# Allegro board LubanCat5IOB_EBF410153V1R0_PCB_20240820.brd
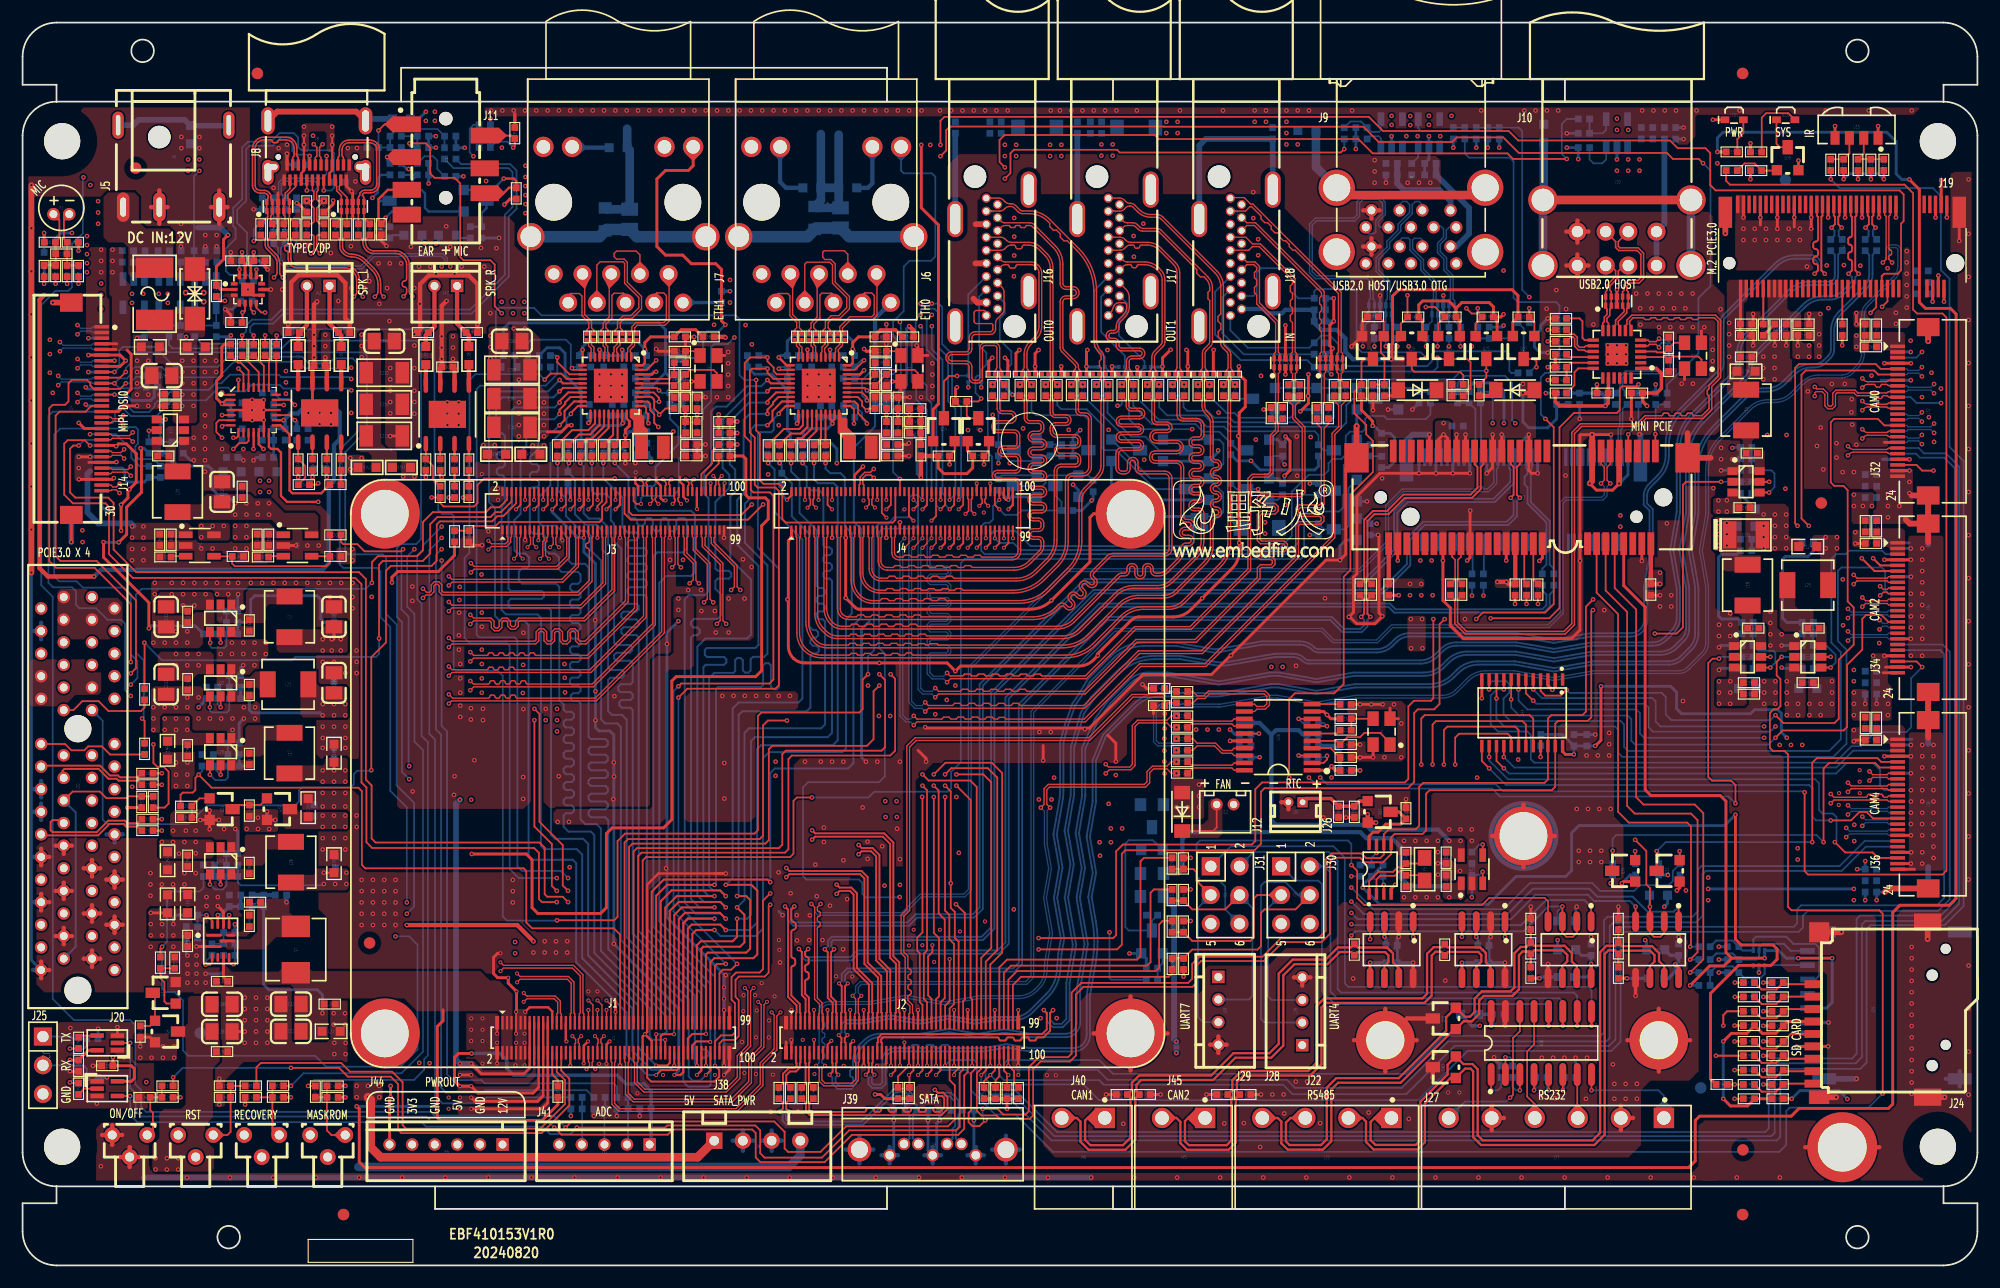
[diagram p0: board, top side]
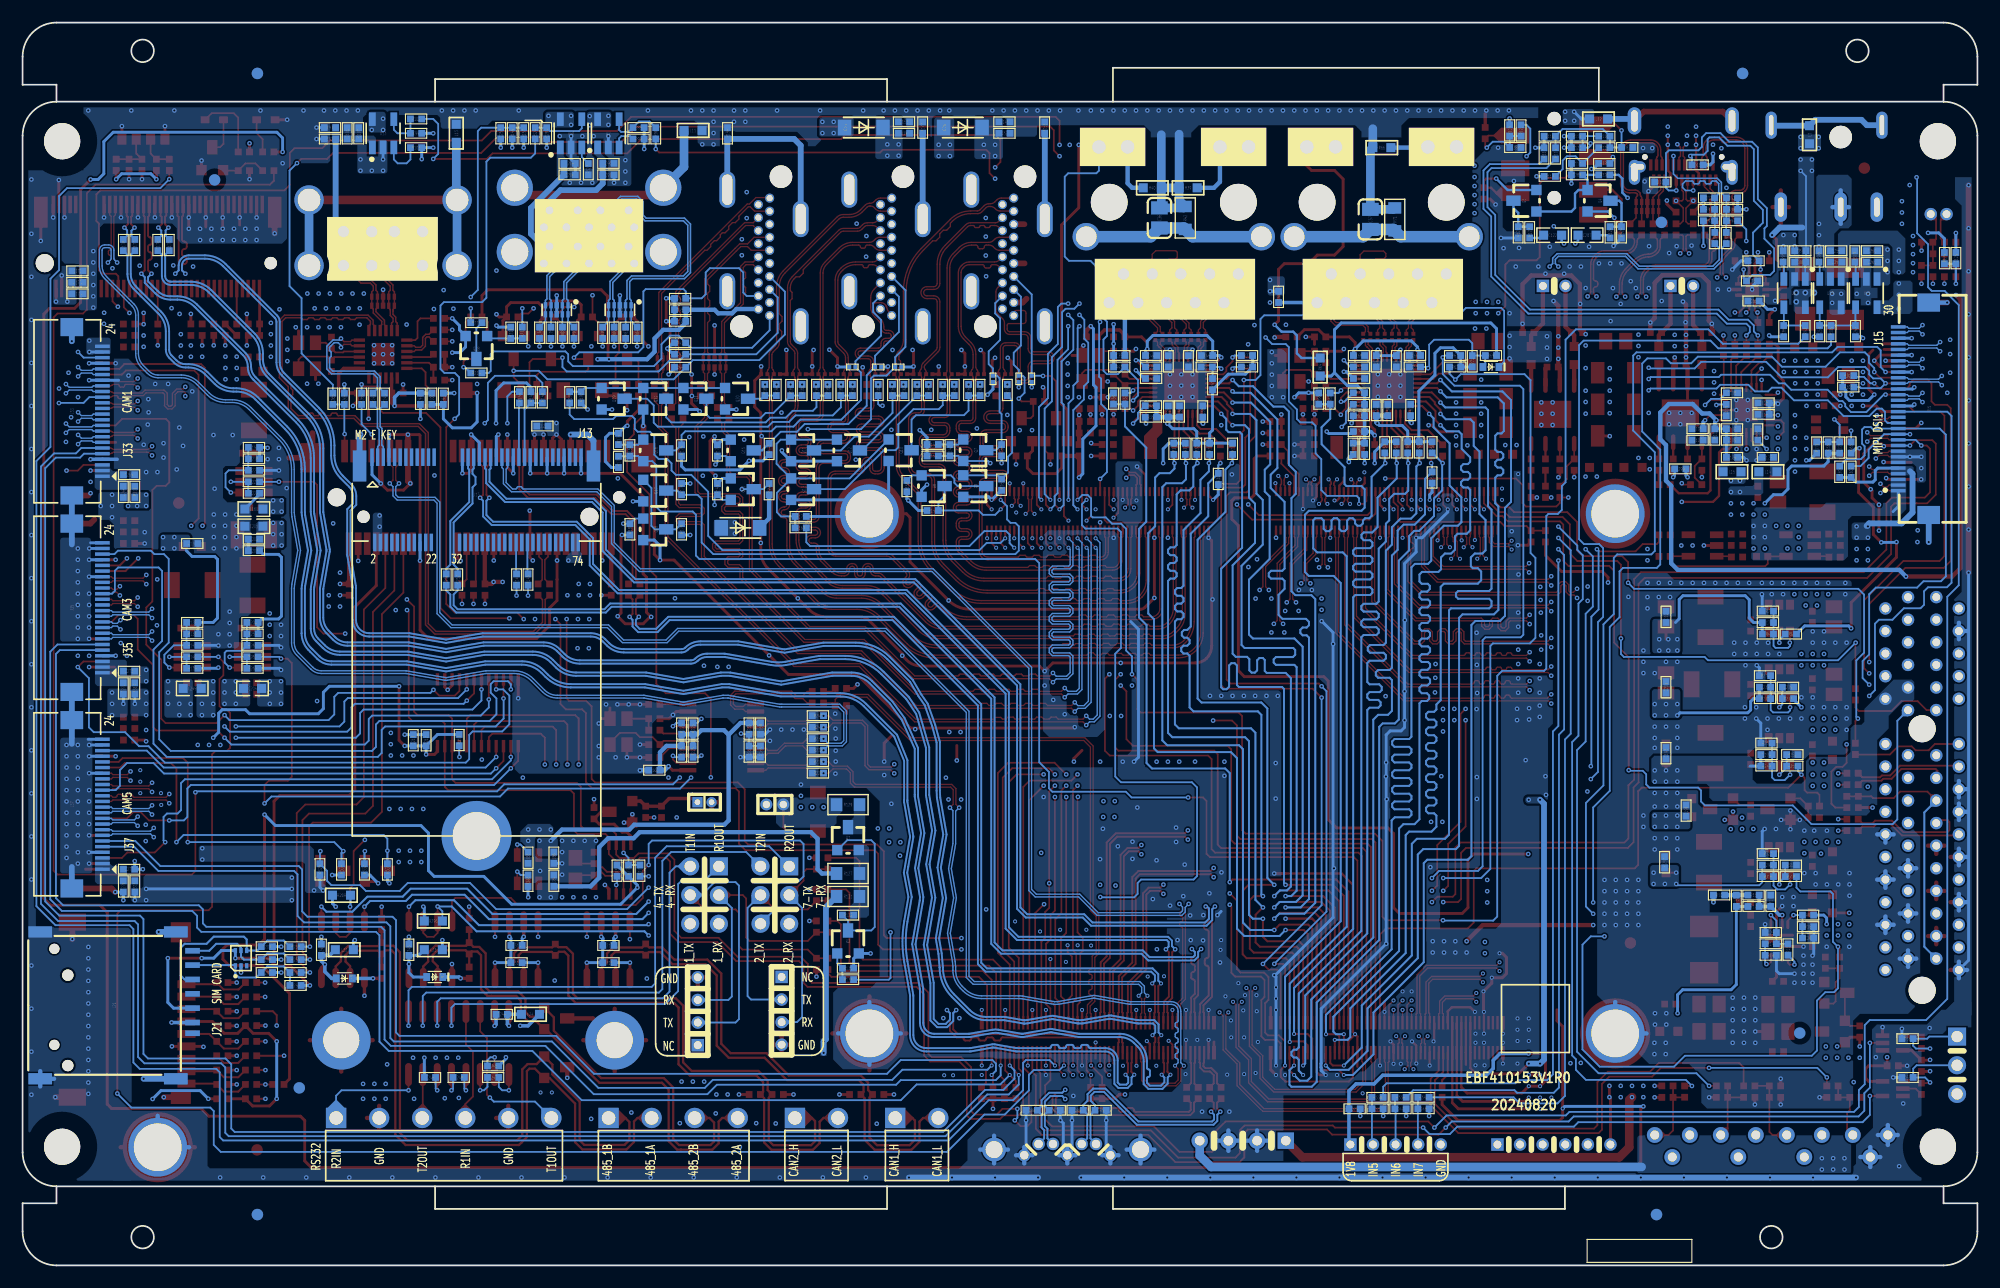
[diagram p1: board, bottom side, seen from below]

Outline 173 x 110 mm; copper layers: TOP, GND02, ART03, ART04, PWR05, BOTTOM. Coordinates in mm from the lower left corner of the outline.
Outline path: circle c10.62,107.5 r1 ; circle c18.24,2.5 r1 ; circle c162.38,107.5 r1 ; circle c162.38,2.5 r1 ; 3,103 arc(0.88,102.12) 0,100 0,10 arc(0.88,7.88) 3,7 ; 3,103 3,104.5 0,104.5 0,107 arc(0.88,109.12) 3,110 170,110 arc(172.12,109.12) 173,107 173,104.5 170,104.5 170,103 ; 3,103 170,103 ; 170,103 arc(172.12,102.12) 173,100 173,10 arc(172.12,7.88) 170,7 ; 3,7 3,5.5 0,5.5 0,3 arc(0.88,0.88) 3,0 170,0 arc(172.12,0.88) 173,3 173,5.5 170,5.5 170,7 ; 3,7 170,7 ; 33.5,103 33.5,106 76.5,106 76.5,103 ; 36.5,7 36.5,5 76.5,5 76.5,7 ; 96.5,103 96.5,105 136.5,105 136.5,103 ; 96.5,7 96.5,5 136.5,5 136.5,7

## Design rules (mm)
net group DP4: nets USB_HUB_DM2 USB_HUB_DP2
net group DP5: nets USB_HUB_DM1 USB_HUB_DP1
net group EKEY_PETN0: nets EKEY_PETN0 PCIE20_1_TXN
net group EKEY_PETP0: nets EKEY_PETP0 PCIE20_1_TXP
net group GMAC0_MCLKINOUT: nets GMAC0_MCLKINOUT PHY1_CLKOUT125
net group GMAC1_MCLKINOUT: nets GMAC1_MCLKINOUT PHY0_CLKOUT125
net group HDMI0_EARC+: nets HDMI0_EARC+ HDMI_TX0_SBDP
net group HDMI0_EARC-: nets HDMI0_EARC- HDMI_TX0_SBDN
net group HDMI1_EARC+: nets HDMI1_EARC+ HDMI_TX1_SBDP
net group HDMI1_EARC-: nets HDMI1_EARC- HDMI_TX1_SBDN
net group HDMI_RX0N_PORT: nets HDMI_RX0N_PORT HDMI_RX_D0N
net group HDMI_RX0P_PORT: nets HDMI_RX0P_PORT HDMI_RX_D0P
net group HDMI_RX1N_PORT: nets HDMI_RX1N_PORT HDMI_RX_D1N
net group HDMI_RX1P_PORT: nets HDMI_RX1P_PORT HDMI_RX_D1P
net group HDMI_RX2N_PORT: nets HDMI_RX2N_PORT HDMI_RX_D2N
net group HDMI_RX2P_PORT: nets HDMI_RX2P_PORT HDMI_RX_D2P
net group HDMI_RXCLKN_PORT: nets HDMI_RX_CLKN HDMI_RXCLKN_PORT
net group HDMI_RXCLKP_PORT: nets HDMI_RX_CLKP HDMI_RXCLKP_PORT
net group HDMI_TX0_D0N: nets HDMI_TX0_D0N HDMI_TX0_D0N_PORT
net group HDMI_TX0_D0P: nets HDMI_TX0_D0P HDMI_TX0_D0P_PORT
net group HDMI_TX0_D1N: nets HDMI_TX0_D1N HDMI_TX0_D1N_PORT
net group HDMI_TX0_D1P: nets HDMI_TX0_D1P HDMI_TX0_D1P_PORT
net group HDMI_TX0_D2N: nets HDMI_TX0_D2N HDMI_TX0_D2N_PORT
net group HDMI_TX0_D2P: nets HDMI_TX0_D2P HDMI_TX0_D2P_PORT
net group HDMI_TX0_D3N: nets HDMI_TX0_D3N HDMI_TX0_D3N_PORT
net group HDMI_TX0_D3P: nets HDMI_TX0_D3P HDMI_TX0_D3P_PORT
net group HDMI_TX1_D0N: nets HDMI_TX1_D0N HDMI_TX1_D0N_PORT
net group HDMI_TX1_D0P: nets HDMI_TX1_D0P HDMI_TX1_D0P_PORT
net group HDMI_TX1_D1N: nets HDMI_TX1_D1N HDMI_TX1_D1N_PORT
net group HDMI_TX1_D1P: nets HDMI_TX1_D1P HDMI_TX1_D1P_PORT
net group HDMI_TX1_D2N: nets HDMI_TX1_D2N HDMI_TX1_D2N_PORT
net group HDMI_TX1_D2P: nets HDMI_TX1_D2P HDMI_TX1_D2P_PORT
net group HDMI_TX1_D3N: nets HDMI_TX1_D3N HDMI_TX1_D3N_PORT
net group HDMI_TX1_D3P: nets HDMI_TX1_D3P HDMI_TX1_D3P_PORT
net group M2PCIE_REF_CLKN: nets M2PCIE_REF_CLKN N16803869
net group M2PCIE_REF_CLKP: nets M2PCIE_REF_CLKP N16803867
net group MDIN0_PHY0: nets MDIN0_PHY0 MDIN0_PHY0_RJ45
net group MDIN0_PHY1: nets MDIN0_PHY1 MDIN0_PHY1_RJ45
net group MDIN1_PHY0: nets MDIN1_PHY0 MDIN1_PHY0_RJ45
net group MDIN1_PHY1: nets MDIN1_PHY1 MDIN1_PHY1_RJ45
net group MDIN2_PHY0: nets MDIN2_PHY0 MDIN2_PHY0_RJ45
net group MDIN2_PHY1: nets MDIN2_PHY1 MDIN2_PHY1_RJ45
net group MDIN3_PHY0: nets MDIN3_PHY0 MDIN3_PHY0_RJ45
net group MDIN3_PHY1: nets MDIN3_PHY1 MDIN3_PHY1_RJ45
net group MDIP0_PHY0: nets MDIP0_PHY0 MDIP0_PHY0_RJ45
net group MDIP0_PHY1: nets MDIP0_PHY1 MDIP0_PHY1_RJ45
net group MDIP1_PHY0: nets MDIP1_PHY0 MDIP1_PHY0_RJ45
net group MDIP1_PHY1: nets MDIP1_PHY1 MDIP1_PHY1_RJ45
net group MDIP2_PHY0: nets MDIP2_PHY0 MDIP2_PHY0_RJ45
net group MDIP2_PHY1: nets MDIP2_PHY1 MDIP2_PHY1_RJ45
net group MDIP3_PHY0: nets MDIP3_PHY0 MDIP3_PHY0_RJ45
net group MDIP3_PHY1: nets MDIP3_PHY1 MDIP3_PHY1_RJ45
net group N16803965: nets N16803965 N16804075
net group PCIE20_1_REFCLK: nets PCIE20_1_REFCLKN PCIE20_1_REFCLKP
net group PCIE20_1_RX: nets PCIE20_1_RXN PCIE20_1_RXP
net group PCIE20_2_REFCLK: nets PCIE20_2_REFCLKN PCIE20_2_REFCLKP
net group PCIE20_2_RX: nets PCIE20_2_RXN PCIE20_2_RXP
net group PCIE20_2_TXN: nets PCIE20_2_TXN PE_TXN
net group PCIE20_2_TXP: nets PCIE20_2_TXP PE_TXP
net group PCIE30_PORT0_REF_CLKN: nets N16803772 PCIE30_PORT0_REF_CLKN
net group PCIE30_PORT0_REF_CLKP: nets N16803735 PCIE30_PORT0_REF_CLKP
net group PCIE30_PORT0_RX0: nets PCIE30_PORT0_RX0N PCIE30_PORT0_RX0P
net group PCIE30_PORT0_RX1: nets PCIE30_PORT0_RX1N PCIE30_PORT0_RX1P
net group PCIE30_PORT0_TX0N: nets PCIE30_PORT0_TX0N PETN0
net group PCIE30_PORT0_TX0P: nets PCIE30_PORT0_TX0P PETP0
net group PCIE30_PORT0_TX1N: nets PCIE30_PORT0_TX1N PETN1
net group PCIE30_PORT0_TX1P: nets PCIE30_PORT0_TX1P PETP1
net group PCIE30_PORT1_REF_CLKN: nets N16810873 PCIE30_PORT1_REF_CLKN
net group PCIE30_PORT1_REF_CLKP: nets N16810864 PCIE30_PORT1_REF_CLKP
net group PCIE30_PORT1_RX0: nets PCIE30_PORT1_RX0N PCIE30_PORT1_RX0P
net group PCIE30_PORT1_RX1: nets PCIE30_PORT1_RX1N PCIE30_PORT1_RX1P
net group PCIE30_PORT1_TX0N: nets PCIE30_PORT1_TX0N PCIEX4_PETN0
net group PCIE30_PORT1_TX0P: nets PCIE30_PORT1_TX0P PCIEX4_PETP0
net group PCIE30_PORT1_TX1N: nets PCIE30_PORT1_TX1N PCIEX4_PETN1
net group PCIE30_PORT1_TX1P: nets PCIE30_PORT1_TX1P PCIEX4_PETP1
net group PCIE30X1_0_CLKREQN_M0: nets N17044551 PCIE30X1_0_CLKREQN_M0
net group PCIE30X1_0_WAKEN_M0: nets N17044511 PCIE30X1_0_WAKEN_M0
net group PCIE30X1_1_CLKREQN_M1: nets N16843974 PCIE30X1_1_CLKREQN_M1
net group PCIE30X1_1_WAKEN_M1: nets N16843960 PCIE30X1_1_WAKEN_M1
net group PCIEX4_REF_CLKN: nets N16810480 PCIEX4_REF_CLKN
net group PCIEX4_REF_CLKP: nets N16810459 PCIEX4_REF_CLKP
net group PWM7_IR_M0: nets N16622302 PWM7_IR_M0
net group RTC_32K_IN: nets N16906410 RTC_32K_IN
net group SATA30_0_RXN: nets SATA30_0_RXN SATA_RXN
net group SATA30_0_RXP: nets SATA30_0_RXP SATA_RXP
net group SATA30_0_TXN: nets SATA30_0_TXN SATA_TXN
net group SATA30_0_TXP: nets SATA30_0_TXP SATA_TXP
net group TYPEC0_SBU1: nets TYPEC0_SBU1 TYPEC_SUB1
net group TYPEC0_SBU2: nets TYPEC0_SBU2 TYPEC_SUB2
net group TYPEC0_SSRX1N: nets TYPEC0_SSRX1N TYPEC_SSRXN1
net group TYPEC0_SSRX1P: nets TYPEC0_SSRX1P TYPEC_SSRXP1
net group TYPEC0_SSRX2N: nets TYPEC0_SSRX2N TYPEC_SSRXN2
net group TYPEC0_SSRX2P: nets TYPEC0_SSRX2P TYPEC_SSRXP2
net group TYPEC0_SSTX1N: nets TYPEC0_SSTX1N TYPEC_SSTXN1
net group TYPEC0_SSTX1P: nets TYPEC0_SSTX1P TYPEC_SSTXP1
net group TYPEC0_SSTX2N: nets TYPEC0_SSTX2N TYPEC_SSTXN2
net group TYPEC0_SSTX2P: nets TYPEC0_SSTX2P TYPEC_SSTXP2
net group TYPEC0_USB20_OTG_DM: nets TYPEC0_USB20_OTG_DM TYPEC_DM
net group TYPEC0_USB20_OTG_DP: nets TYPEC0_USB20_OTG_DP TYPEC_DP
net group TYPEC1_SSRX1: nets TYPEC1_SSRX1N TYPEC1_SSRX1P
net group TYPEC1_SSTX1: nets TYPEC1_SSTX1N TYPEC1_SSTX1P
net group TYPEC1_USB20_OTG_DM: nets TYPEC1_USB20_OTG_DM USB30_DM
net group TYPEC1_USB20_OTG_DP: nets TYPEC1_USB20_OTG_DP USB30_DP
net group USB20_DM1: nets USB20_DM1 USB20_HOST0_DM
net group USB20_DP1: nets USB20_DP1 USB20_HOST0_DP
net group USB20_HOST1_DM: nets N16621978 USB20_HOST1_DM
net group USB20_HOST1_DP: nets N16621974 USB20_HOST1_DP
net group USB30_RX: nets USB30_RXN USB30_RXP
net group USB30_TX: nets USB30_TXN USB30_TXP
net group USB_HUB_DM3: nets N16844509 USB_HUB_DM3
net group USB_HUB_DM4: nets N17044768 USB_HUB_DM4
net group USB_HUB_DP3: nets N16844471 USB_HUB_DP3
net group USB_HUB_DP4: nets N17044766 USB_HUB_DP4
net group 50_OHM: nets GMAC0_RXCLK GMAC0_RXD0 GMAC0_RXD1 GMAC0_RXD2 GMAC0_RXD3 GMAC0_RXDV_CRS GMAC1_RXCLK GMAC1_RXD0 GMAC1_RXD1 GMAC1_RXD2 GMAC1_RXD3 GMAC1_RXDV_CRS SDMMC_CLK SDMMC_CMD SDMMC_D0 SDMMC_D1 SDMMC_D2 SDMMC_D3
net group GMAC0_RXCLK: nets N16613010
net group GMAC0_RXD0: nets N16612988
net group GMAC0_RXD1: nets N16612992
net group GMAC0_RXD2: nets N16612996
net group GMAC0_RXD3: nets N16613006
net group GMAC0_RXDV_CRS: nets N16613014
net group GMAC1_RXCLK: nets N16607264
net group GMAC1_RXD0: nets N16607242
net group GMAC1_RXD1: nets N16607246
net group GMAC1_RXD2: nets N16607250
net group GMAC1_RXD3: nets N16607260
net group GMAC1_RXDV_CRS: nets N16607268
net group HDMI_GND: nets N16778784 N16781438 N16783799
net group PWR: nets 1V05_AVDD_PHY1 1V05_DVDD_PHY0 1V05_DVDD_PHY1 1V8_DVDD_PHY1 3V3_AVDD_PHY0 3V3_AVDD_PHY1 3V3_DVDD_PHY0 3V3_DVDD_PHY1 RS232_3V3 RS485_2_3V3 SIM_VDD VCC3V3_SD_S3 VCC_RTC
net group SDMMC_CLK: nets SD_CLK
net group SDMMC_CMD: nets SD_CMD
net group SDMMC_D0: nets SD_DAT0
net group SDMMC_D1: nets SD_DAT1
net group SDMMC_D2: nets SD_DAT2
net group SDMMC_D3: nets SD_DAT3
net group VCC3V3_PCIECLK: nets N16803673
net group VCC_3V3_S3: nets N16622154

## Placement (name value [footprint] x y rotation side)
C1  10uF  [C0603]  11.3 81.29 180 top
C2  10uF  [C0603]  15.37 81.29 0 top
C3  0.1uF  [C0402]  13.08 77.1 180 top
C4  NC  [C0402]  27.43 15.89 0 top
C5  NC  [C0402]  20.19 14.87 180 top
C6  0.1uF  [C0402]  20.07 56.64 90 top
C7  NC  [C0402]  18.54 56.89 0 bottom
C8  22uF  [C0805]  27.56 57.4 90 top
C9  10uF  [C0402]  152.78 14.75 180 top
C10  0.1uF  [C0402]  152.78 21.22 180 top
C11  0.1uF  [C0402]  27.56 57.4 90 bottom
C12  22uF  [C0805]  12.7 57.4 270 top
C13  0.1uF  [C0402]  14.61 57.4 270 top
C14  0.1uF  [C0402]  20.07 50.93 90 top
C15  0.1uF  [C0402]  17.91 15.89 180 top
C16  0.22uF  [C0402]  20.57 32.15 0 top
C17  10uF  [C0603]  12.83 32 90 top
C18  10uF  [C0603]  14.61 32.02 90 top
C19  0.1uF  [C0402]  14.61 28.72 270 top
C20  NC  [C0402]  21.34 32.27 270 bottom
C21  47uF  [C0805]  23.75 20.72 180 top
C22  47uF  [C0805]  23.75 23.13 180 top
C23  22uF  [C0603]  27.3 20.72 0 top
C24  0.1uF  [C0402]  27.18 23.13 0 top
C25  1uF  [C0402]  18.29 29.46 0 bottom
C26  0.1uF  [C0402]  14.99 28.97 180 bottom
C27  0.1uF  [C0402]  17.65 25.14 180 top
C28  0.1uF  [C0402]  12.83 14.87 0 top
C29  0.1uF  [C0402]  71.6 75.58 90 bottom
C30  0.1uF  [C0402]  70.61 75.58 90 bottom
C31  0.1uF  [C0402]  76.96 72.66 0 top
C32  4.7uF  [C0402]  76.96 71.64 0 top
C33  18pF  [C0402]  75.95 80.91 180 top
C34  18pF  [C0402]  76.45 78.37 270 top
C35  0.1uF  [C0402]  75.95 80.53 0 bottom
C36  1nF  [C0805]  72.39 92.71 90 bottom
C37  0.1uF  [C0402]  68.2 79.52 0 bottom
C38  0.1uF  [C0402]  68.55 75.58 90 bottom
C39  0.1uF  [C0402]  76.45 76.34 90 top
C40  0.1uF  [C0402]  71.6 80.02 270 bottom
C41  0.1uF  [C0402]  73.13 78.5 180 bottom
C42  0.1uF  [C0402]  77.47 76.34 90 top
C43  0.1uF  [C0402]  69.82 80.02 270 bottom
C44  0.1uF  [C0402]  73.13 80.53 180 bottom
C45  0.1uF  [C0402]  75.95 82.18 0 top
C46  0.1uF  [C0402]  68.17 80.53 0 bottom
C47  0.1uF  [C0402]  78.99 73.67 180 top
C48  0.1uF  [C0402]  78.99 75.83 180 top
C49  0.1uF  [C0402]  78.99 74.69 180 top
C50  0.1uF  [C0402]  52.19 75.71 90 bottom
C51  0.1uF  [C0402]  53.2 75.71 90 bottom
C52  0.1uF  [C0402]  59.18 72.66 0 top
C53  4.7uF  [C0402]  59.18 71.64 0 top
C54  18pF  [C0402]  58.17 80.91 180 top
C55  18pF  [C0402]  58.67 78.37 270 top
C56  0.1uF  [C0402]  61.85 85.72 90 bottom
C57  1nF  [C0805]  53.72 92.58 90 bottom
C58  0.1uF  [C0402]  49.78 79.52 0 bottom
C59  0.1uF  [C0402]  62.1 74.69 0 top
C60  0.1uF  [C0402]  59.69 76.34 90 top
C61  0.1uF  [C0402]  50.15 75.71 90 bottom
C62  0.1uF  [C0402]  51.42 80.02 270 bottom
C63  0.1uF  [C0402]  53.2 80.02 270 bottom
C64  0.1uF  [C0402]  54.73 78.5 180 bottom
C65  0.1uF  [C0402]  58.67 76.34 90 top
C66  0.1uF  [C0402]  49.77 80.53 0 bottom
C67  0.1uF  [C0402]  58.17 82.18 0 top
C68  0.1uF  [C0402]  54.73 80.53 180 bottom
C69  0.1uF  [C0402]  53.34 72.15 270 top
C70  0.1uF  [C0402]  54.74 73.8 0 bottom
C71  0.1uF  [C0402]  54.23 72.28 270 bottom
C72  10uF  [C0402]  18.92 88.91 180 top
C73  0.1uF  [C0402]  20.95 88.91 0 top
C74  0.1uF  [C0402]  17.14 86.25 270 top
C75  0.1uF  [C0402]  126.24 82.55 270 bottom
C76  0.1uF  [C0402]  127.25 82.55 270 bottom
C77  220pF  [C0402]  19.81 88.91 0 bottom
C78  220pF  [C0402]  19.94 87.14 180 bottom
C79  0.1uF  [C0402]  28.7 91.69 270 top
C80  0.1uF  [C0402]  27.69 91.69 270 top
C81  1uF  [C0402]  19.81 85.36 0 bottom
C82  0.1uF  [C0402]  22.1 91.69 270 top
C83  0.1uF  [C0402]  21.08 91.69 270 top
C84  0.1uF  [C0402]  23.24 90.93 270 bottom
C85  0.1uF  [C0402]  22.23 90.93 270 bottom
C86  0.1uF  [C0402]  17.14 82.69 270 bottom
C87  10uF  [C0402]  15.67 89.81 0 bottom
C88  0.1uF  [C0402]  15.67 88.8 0 bottom
C89  0.1uF  [C0402]  118.49 100.71 180 bottom
C90  10uF  [C0402]  121.16 97.53 180 bottom
C91  0.1uF  [C0402]  121.16 96.52 180 bottom
C92  1uF  [C0402]  145.8 99.69 0 bottom
C93  0.1uF  [C0402]  135.76 76.71 90 bottom
C94  4.7uF  [C0402]  137.79 76.71 270 bottom
C95  0.1uF  [C0402]  139.83 77.21 180 top
C96  0.1uF  [C0402]  142.88 77.21 180 top
C97  1uF  [C0402]  145.8 100.71 0 bottom
C98  0.1uF  [C0402]  136.14 78.36 180 top
C99  0.1uF  [C0402]  138.18 100.2 180 bottom
C100  10uF  [C0402]  143.26 100.2 90 bottom
C101  0.1uF  [C0402]  144.27 100.2 90 bottom
C102  NC  [C0402]  145.67 79.63 270 top
C103  NC  [C0402]  145.67 81.66 90 top
C104  0.1uF  [C0402]  162.43 97.41 270 top
C105  4.7uF  [C0402]  163.58 97.41 270 top
C106  0.1uF  [C0402]  24.77 74.06 0 bottom
C107  4.7uF  [C0402]  24.77 73.04 0 bottom
C108  0.1uF  [C0402]  18.92 76.34 0 bottom
C109  0.1uF  [C0402]  21.72 73.04 180 bottom
C110  4.7uF  [C0402]  21.72 74.06 180 bottom
C111  10uF  [C0402]  35.43 97.53 0 bottom
C112  1uF  [C0402]  19.43 81.02 90 top
C113  1uF  [C0402]  20.45 81.02 90 top
C114  0.1uF  [C0402]  18.92 75.33 0 bottom
C115  1uF  [C0402]  21.46 81.02 90 top
C116  270pF  [C0402]  37.85 99.95 0 bottom
C117  1uF  [C0402]  22.48 81.02 90 top
C118  10uF  [C0402]  21.72 77.23 180 bottom
C119  10uF  [C0402]  22.23 75.71 270 bottom
C120  10uF  [C0402]  19.43 73.55 90 bottom
C121  NC  [C0402]  35.43 98.93 0 bottom
C122  47uF  [C0603]  37.59 91.18 0 bottom
C123  10uF  [C0402]  18.54 71.52 0 bottom
C124  10uF  [C0402]  21.72 71.52 180 bottom
C125  4.7uF  [C0402]  1.91 89.15 90 bottom
C126  100pF  [C0402]  3.43 89.53 0 top
C127  0.1uF  [C0402]  158.5 56.4 180 top
C128  NC  [C0402]  157.99 56.91 180 bottom
C129  22uF  [C0603]  157.99 63.63 180 top
C130  0.1uF  [C0402]  157.99 63.9 180 bottom
C131  0.22uF  [C0402]  96.06 77.47 90 top
C132  0.22uF  [C0402]  95.05 77.47 90 top
C133  0.22uF  [C0402]  93.83 77.47 90 top
C134  0.22uF  [C0402]  92.81 77.47 90 top
C135  0.22uF  [C0402]  91.57 77.47 90 top
C136  0.22uF  [C0402]  90.55 77.47 90 top
C137  0.22uF  [C0402]  89.28 77.47 90 top
C138  0.22uF  [C0402]  88.27 77.47 90 top
C139  1uF  [C0402]  86.87 77.47 90 top
C140  1uF  [C0402]  85.85 77.47 90 top
C141  1uF  [C0402]  86.11 101.22 180 bottom
C142  100pF  [C0402]  90.93 72.15 270 bottom
C143  0.22uF  [C0402]  107.29 77.47 90 top
C144  0.22uF  [C0402]  106.27 77.47 90 top
C145  0.22uF  [C0402]  105.03 77.47 90 top
C146  0.22uF  [C0402]  104.01 77.47 90 top
C147  0.22uF  [C0402]  102.79 77.47 90 top
C148  0.22uF  [C0402]  101.78 77.47 90 top
C149  0.22uF  [C0402]  100.56 77.47 90 top
C150  0.22uF  [C0402]  99.54 77.47 90 top
C151  1uF  [C0402]  98.3 77.47 90 top
C152  1uF  [C0402]  97.28 77.47 90 top
C153  1uF  [C0402]  95 101.22 180 bottom
C154  100pF  [C0402]  119.25 72.13 270 bottom
C155  1uF  [C0402]  114.81 83.56 0 bottom
C156  0.1uF  [C0402]  153.03 71.9 180 top
C157  NC  [C0402]  152.53 72.4 180 bottom
C158  22uF  [C0603]  152.53 79.14 0 top
C159  0.1uF  [C0402]  152.53 80.41 0 top
C160  22uF  [C0603]  152.53 66.94 0 bottom
C161  0.1uF  [C0402]  152.4 67.07 0 top
C162  1uF  [C0402]  117.09 43.83 0 bottom
C163  0.1uF  [C0402]  117.09 43.81 0 top
C164  18pF  [C0402]  117.09 46.1 0 top
C165  18pF  [C0402]  117.09 48.39 180 top
C166  0.1uF  [C0402]  107.7 45.48 270 bottom
C167  1uF  [C0402]  108.71 45.48 270 bottom
C168  4.7uF  [C0402]  107.7 47.51 270 bottom
C169  0.1uF  [C0402]  157.61 83.33 0 top
C170  0.1uF  [C0402]  152.53 83.33 0 top
C171  0.1uF  [C0402]  152.53 82.31 0 top
C172  0.1uF  [C0402]  168.15 88.03 180 bottom
C173  0.1uF  [C0402]  168.15 87.01 180 bottom
C174  0.1uF  [C0402]  168.15 85.99 180 bottom
C175  0.22uF  [C0402]  160.02 90.31 90 bottom
C176  0.22uF  [C0402]  161.04 90.31 90 bottom
C177  0.22uF  [C0402]  163.07 90.31 90 bottom
C178  0.22uF  [C0402]  164.08 90.31 90 bottom
C179  0.1uF  [C0402]  20.07 44.83 90 top
C180  22uF  [C0603]  27.56 45.34 90 top
C181  0.1uF  [C0402]  157.61 82.31 0 top
C182  0.1uF  [C0402]  155.07 82.82 270 top
C183  0.1uF  [C0402]  156.08 82.82 270 top
C184  4.7uF  [C0402]  125.98 34.05 90 bottom
C185  0.1uF  [C0402]  125.98 34.05 90 top
C186  4.7uF  [C0402]  125.98 36.08 270 bottom
C187  0.1uF  [C0402]  125.98 36.08 270 top
C188  NC  [C0402]  128.27 36.08 270 bottom
C189  0.22uF  [C0402]  11.05 43.56 180 top
C190  0.22uF  [C0402]  11.05 42.54 180 top
C191  0.22uF  [C0402]  11.05 39.5 180 top
C192  0.22uF  [C0402]  11.05 38.48 180 top
C193  0.1uF  [C0402]  27.56 45.34 90 bottom
C194  NC  [C0402]  18.67 45.21 0 bottom
C195  22uF  [C0603]  12.83 45.59 270 top
C196  0.1uF  [C0402]  14.61 45.59 270 top
C197  22uF  [C0603]  25.27 40.51 90 top
C198  0.1uF  [C0402]  25.78 40.26 90 bottom
C199  0.1uF  [C0402]  153.16 56.4 0 top
C200  NC  [C0402]  152.65 56.91 0 bottom
C201  22uF  [C0603]  152.53 65.42 0 bottom
C202  1uF  [C0402]  152.53 64.28 0 bottom
C203  0.1uF  [C0402]  152.53 63.26 0 bottom
C204  22uF  [C0603]  152.65 51.07 0 bottom
C205  10uF  [C0402]  152.78 50.56 0 top
C206  0.1uF  [C0402]  152.78 51.58 0 top
C207  33pF  [C0402]  151.38 25.92 180 bottom
C208  33pF  [C0402]  151.38 27.07 180 bottom
C209  33pF  [C0402]  151.38 28.21 180 bottom
C210  47uF  [C1206]  32 79.01 0 top
C211  47uF  [C1206]  32 73.42 0 top
C212  10uF  [C0402]  137.29 46.48 90 bottom
C213  0.1uF  [C0402]  138.43 46.48 90 bottom
C214  0.1uF  [C0402]  119.38 59.82 90 top
C215  0.1uF  [C0402]  118.36 59.82 90 top
C216  0.1uF  [C0402]  121.16 26.8 0 bottom
C217  0.1uF  [C0402]  121.16 28.32 0 bottom
C218  47uF  [C1206]  32 76.21 0 top
C219  22uF  [C0805]  32 81.8 0 top
C220  0.1uF  [C0402]  120.9 59.82 270 top
C221  0.1uF  [C0402]  132.08 59.82 270 top
C222  0.1uF  [C0402]  127 74.29 0 bottom
C223  0.1uF  [C0402]  144.1 59.82 270 top
C224  0.1uF  [C0402]  12.45 71.64 0 top
C225  NC  [C0402]  12.19 72.39 270 bottom
C226  22uF  [C0805]  17.65 68.47 90 top
C227  0.1uF  [C0402]  19.43 68.47 90 top
C228  22uF  [C0805]  12.32 78.75 180 top
C229  0.1uF  [C0402]  13.08 76.09 180 top
C230  22uF  [C0805]  27.56 51.56 90 top
C231  0.1uF  [C0402]  27.56 51.18 90 bottom
C232  NC  [C0402]  18.8 51.18 0 bottom
C233  22uF  [C0805]  12.7 51.43 270 top
C234  0.1uF  [C0402]  14.61 51.43 270 top
C235  0.1uF  [C0402]  4.95 17.67 270 top
C236  0.1uF  [C0402]  7.49 17.67 180 top
C237  0.1uF  [C0402]  122.43 40.02 90 top
C238  10uF  [C0402]  117.86 40.15 270 top
C239  0.1uF  [C0402]  16.76 51.18 180 bottom
C240  18pF  [C0402]  122.43 36.07 90 top
C241  18pF  [C0402]  122.43 34.03 270 top
C242  0.1uF  [C0402]  146.56 27.94 90 bottom
C243  0.1uF  [C0402]  138.81 27.94 90 bottom
C244  0.1uF  [C0402]  130.6 22.22 0 bottom
C245  0.1uF  [C0402]  131.36 17.65 180 bottom
C246  0.1uF  [C0402]  136.95 16.64 0 bottom
C247  0.1uF  [C0402]  131.36 16.64 180 bottom
C248  0.1uF  [C0402]  134.41 16.64 180 bottom
C249  22uF  [C0603]  157.99 51.07 0 bottom
C250  0.1uF  [C0402]  157.99 51.58 0 top
C251  0.1uF  [C0402]  135.51 60.7 90 bottom
C252  0.1uF  [C0402]  134.49 60.7 90 bottom
C253  0.1uF  [C0402]  130.68 100.2 270 bottom
C254  10uF  [C0402]  20.77 64.23 270 top
C255  0.1uF  [C0402]  21.78 64.23 270 top
C256  10uF  [C0402]  12.5 89.81 0 bottom
C257  0.1uF  [C0402]  12.5 88.8 0 bottom
C258  0.1uF  [C0402]  27.69 62.75 0 top
C259  0.1uF  [C0402]  13.97 82.69 270 bottom
C260  10uF  [C0402]  9.32 89.81 0 bottom
C261  0.1uF  [C0402]  9.32 88.8 0 bottom
C262  0.1uF  [C0402]  10.79 82.69 270 bottom
C263  10uF  [C0402]  12.13 64.23 270 top
C264  0.1uF  [C0402]  13.15 64.23 270 top
C265  0.1uF  [C0402]  19.05 62.75 0 top
C266  10uF  [C0402]  164.08 68.47 270 bottom
C267  10uF  [C0402]  164.08 82.82 90 top
C268  0.1uF  [C0402]  163.58 81.29 180 top
C269  0.1uF  [C0402]  163.58 69.99 180 bottom
C270  10uF  [C0402]  164.08 65.42 90 top
C271  0.1uF  [C0402]  163.58 63.9 180 top
C272  10uF  [C0402]  164.08 51.07 270 bottom
C273  0.1uF  [C0402]  163.58 52.59 180 bottom
C274  10uF  [C0402]  164.08 48.02 90 top
C275  0.1uF  [C0402]  163.58 46.5 180 top
C276  10uF  [C0402]  164.08 33.54 270 bottom
C277  0.1uF  [C0402]  163.58 35.07 180 bottom
C278  0.1uF  [C0402]  26.29 79.64 180 top
C279  0.1uF  [C0402]  27.69 69.1 0 top
C280  22uF  [C0805]  17.65 23.11 0 top
C281  22uF  [C0805]  17.65 20.7 0 top
C282  0.1uF  [C0402]  17.65 18.92 0 top
C283  0.1uF  [C0402]  20.07 35.18 90 top
C284  0.1uF  [C0402]  126.62 100.2 270 bottom
C285  10uF  [C0402]  124.59 97.53 180 bottom
C286  0.1uF  [C0402]  124.59 96.52 180 bottom
C287  47uF  [C0603]  34.54 91.18 180 bottom
C288  0.1uF  [C0402]  40.89 98.95 180 bottom
C289  0.1uF  [C0402]  35.43 96.52 0 bottom
C290  NC  [C0402]  18.54 35.43 0 bottom
C291  22uF  [C0603]  27.56 35.56 90 top
C292  0.1uF  [C0402]  27.69 35.69 90 bottom
C293  22uF  [C0603]  12.83 35.81 270 top
C294  0.1uF  [C0402]  14.61 35.81 270 top
C295  10nF  [C0402]  68.96 15.25 270 top
C296  10nF  [C0402]  69.98 15.25 270 top
C297  10nF  [C0402]  67.94 15.25 270 top
C298  10nF  [C0402]  66.93 15.25 270 top
C299  0.1uF  [C0402]  26.29 70.5 0 bottom
C300  1nF  [C0402]  24 82.56 180 top
C301  1nF  [C0402]  28.45 82.56 0 top
C302  1uF  [C0402]  25.65 70.88 270 top
C303  47uF  [C1206]  43.31 74.18 0 top
C304  47uF  [C1206]  43.31 76.72 0 top
C305  47uF  [C1206]  43.31 79.26 0 top
C306  22uF  [C0805]  43.31 81.8 0 top
C307  0.1uF  [C0402]  37.59 79.52 180 top
C308  0.1uF  [C0402]  39.5 68.47 90 top
C309  0.1uF  [C0402]  38.23 68.47 90 top
C310  1nF  [C0402]  35.43 82.56 180 top
C311  1nF  [C0402]  39.75 82.56 0 top
C312  1uF  [C0402]  36.96 70.88 270 top
C313  0.1uF  [C0402]  129.29 26.8 0 bottom
C314  0.1uF  [C0402]  129.29 28.32 0 bottom
C315  220uF  [CASE-B_3528]  152.53 64.66 0 top
C316  NC  [C0402]  119.51 83.96 180 top
D1  SMAJ13CA  [SMA_CA]  15.24 85.99 270 top
D2  D2315-3R3  [ESD0402]  27.43 14.87 180 top
D3  D2315-3R3  [ESD0402]  22.61 14.87 180 top
D4  D2315-3R3  [ESD0402]  17.91 14.87 0 top
D5  D1250-5R5C  [R0201]  88.19 78.88 0 top
D6  D2315-3R3  [ESD0402]  10.79 14.87 0 top
D7  RB521S-30  [SOD523]  43.05 79.52 0 bottom
D8  D2315-5R0B  [ESD0402]  26.67 93.72 90 top
D9  D2315-5R0B  [ESD0402]  25.15 93.72 90 top
D10  D2315-5R0B  [ESD0402]  28.07 95.88 180 bottom
D11  D2315-5R0B  [ESD0402]  24.77 97.41 0 bottom
D12  D2315-5R0B  [ESD0402]  23.75 94.49 180 bottom
D13  D2315-5R0B  [ESD0402]  21.72 94.49 0 bottom
D14  D1250-5R5C  [R0201]  89.33 78.88 180 top
D15  1N4148W  [SOD-123]  102.62 40.15 270 top
D16  D2315-5R0B  [ESD0402]  155.32 16.02 0 top
D17  D2315-5R0B  [ESD0402]  155.32 17.29 0 top
D18  D2315-5R0B  [ESD0402]  155.32 18.56 0 top
D19  D2315-5R0B  [ESD0402]  155.32 19.83 0 top
D20  D2315-5R0B  [ESD0402]  155.32 22.49 0 top
D21  D2315-5R0B  [ESD0402]  155.32 23.76 0 top
D22  D2315-5R0B  [ESD0402]  155.32 25.03 0 top
D23  D2315-3R3  [ESD0402]  155.32 21.21 180 top
D24  D2315-3R3  [ESD0402]  55.12 13.86 180 bottom
D25  D2315-3R3  [ESD0402]  53.09 13.86 180 bottom
D26  1N5819W  [SOD-123]  89.79 100.71 180 bottom
D27  D1250-5R5C  [R0201]  85.78 78.88 0 top
D28  D1250-5R5C  [R0201]  87.12 78.47 90 bottom
D29  D1250-5R5C  [R0201]  84.84 78.47 90 bottom
D30  D1250-5R5C  [R0201]  86.92 78.88 180 top
D31  D1250-5R5C  [R0201]  83.69 78.47 90 bottom
D32  D2315-5R0B  [ESD0402]  86.11 100.2 0 bottom
D33  1N5819W  [SOD-123]  98.55 100.71 180 bottom
D34  D1250-5R5C  [R0201]  97.26 78.88 0 top
D35  D1250-5R5C  [R0201]  99.57 79.52 180 bottom
D36  D1250-5R5C  [R0201]  97.28 79.52 0 bottom
D37  D1250-5R5C  [R0201]  98.37 78.88 180 top
D38  D1250-5R5C  [R0201]  95.5 79.52 0 bottom
D39  D2315-5R0B  [ESD0402]  95 100.2 0 bottom
D40  1N5819W  [SOD-123]  123.44 77.47 0 top
D41  D2315-5R0B  [ESD0402]  114.81 81.66 180 bottom
D42  D2315-5R0B  [ESD0402]  114.81 85.6 180 bottom
D43  D2315-5R0B  [ESD0402]  114.81 80.64 180 bottom
D44  D2315-5R0B  [ESD0402]  114.81 79.5 180 bottom
D45  D2315-5R0B  [ESD0402]  114.81 84.58 180 bottom
D46  1N5819W  [SOD-123]  132.08 77.47 180 top
D47  D2315-3R3  [ESD0402]  51.05 13.86 180 bottom
D48  D2315-3R3  [ESD0402]  49.02 13.86 180 bottom
D49  1N5819W  [SOD-123]  109.47 65.28 180 bottom
D50  D1250-5R5C  [R0201]  90.5 78.88 0 top
D51  D1250-5R5C  [R0201]  91.64 78.88 180 top
D52  D1250-5R5C  [R0201]  92.76 78.88 0 top
D53  D1250-5R5C  [R0201]  93.88 78.88 180 top
D54  D1250-5R5C  [R0201]  95 78.88 0 top
D55  D2315-3R3  [ESD0402]  6.18 16.64 0 bottom
D56  D2315-3R3  [ESD0402]  6.18 20.06 0 bottom
D57  BAT54C  [SOT23]  120.03 40.15 270 top
D58  RB521S-30  [SOD523]  144.53 25.4 0 bottom
D59  D2315-3R3  [ESD0402]  116.46 40.15 270 top
D60  RB521S-30  [SOD523]  136.53 25.53 0 bottom
D61  D2315-3R3  [ESD0402]  102.74 32.78 90 top
D62  D2315-3R3  [ESD0402]  102.74 35.57 90 top
D63  D2315-3R3  [ESD0402]  102.74 26.68 270 top
D64  D2315-3R3  [ESD0402]  102.74 29.99 90 top
D65  D1250-5R5C  [R0201]  96.14 78.88 180 top
D66  D1250-5R5C  [R0201]  99.49 78.88 0 top
D67  D1250-5R5C  [R0201]  100.61 78.88 180 top
D68  D1250-5R5C  [R0201]  101.73 78.88 0 top
D69  D1250-5R5C  [R0201]  102.84 78.88 180 top
D70  D1250-5R5C  [R0201]  103.96 78.88 0 top
D71  D1250-5R5C  [R0201]  105.11 78.88 180 top
D72  D1250-5R5C  [R0201]  106.25 78.88 0 top
D73  D1250-5R5C  [R0201]  107.37 78.88 180 top
D74  D2315-5R0B  [ESD0402]  97.28 15.13 0 top
D75  D2315-5R0B  [ESD0402]  99.31 15.13 180 top
D76  D2315-5R0B  [ESD0402]  106.17 15.13 0 top
D77  D2315-5R0B  [ESD0402]  108.2 15.13 180 top
D78  D2315-5R0B  [ESD0402]  4.45 90.57 180 top
D79  D2315-5R0B  [ESD0402]  43.69 94.88 90 top
D80  D2315-5R0B  [ESD0402]  31.75 91.71 90 top
D81  D2315-5R0B  [ESD0402]  43.56 100.22 270 top
D82  D2315-5R0B  [ESD0402]  30.99 98.95 0 bottom
D83  D2315-5R0B  [ESD0402]  2.41 90.57 0 top
D85  D2315-5R0B  [ESD0402]  77.6 13.73 0 bottom
D86  D2315-5R0B  [ESD0402]  79.63 13.73 180 bottom
D87  D2315-5R0B  [ESD0402]  81.66 13.73 0 bottom
D88  D2315-5R0B  [ESD0402]  83.69 13.73 180 bottom
DN1  SM712  [SOT23]  125.84 21.86 90 top
DN2  SM712  [SOT23]  125.84 17.54 90 top
F1  SMD1812P200TF16  [F1812]  11.68 85.99 270 top
J1  DF40C-100DP-0.4V(51)  [DF40C-100DP-0P4V]  52.27 20.15 0 top
J2  DF40C-100DP-0.4V(51)  [DF40C-100DP-0P4V]  77.84 20.15 0 top
J3  DF40C-100DS-0.4V(51)  [DF40HC-100DS-0P4V]  52.27 66.79 0 top
J4  DF40C-100DS-0.4V(51)  [DF40HC-100DS-0P4V]  77.84 66.79 0 top
J5  DC-044A-20A  [DC_IN_TH_3P_10R1X11R6]  13.35 98.17 270 top
J6  -  [HY911130A]  71.12 94.1 0 top
J7  -  [HY911130A]  52.72 94.1 0 top
J8  TYPE-C  [USB-C-SMD_TYC-324G]  26.03 98.68 180 top
J9  USB3D0_USB2D0-A-D  [USB3D0-AF-18P]  122.87 91.88 180 top
J10  -  [USB-A-D]  141.1 95 0 top
J11  PJ-393  [AUDIO_SMD_7P_6R0X8R8]  37.45 97 180 top
J12  A1501WV-2P  [ZH1P5MM_TH_2P]  106.43 40.8 0 top
J13  -  [M2_NGFF_E_KEY]  132.83 67.76 180 bottom
J14  FPC_0R5_30P_D  [FPC-30P-0P5]  5.66 75.82 270 top
J15  FPC_0R5_30P_D  [FPC-30P-0P5]  5.66 75.82 90 bottom
J16  HDMI-001C  [HDMI-SMD]  85.79 89.16 90 top
J17  HDMI-001C  [HDMI-SMD]  96.59 89.16 90 top
J18  HDMI-001C  [HDMI-SMD]  107.39 89.16 90 top
J19  -  [M2_NGFF_M_KEY]  161.04 90.18 0 top
J20  AAA-PCI-161-K03  [PCIE_64PIN_1R00]  4.89 41.15 270 top
J21  SIM-7-1  [NANO_SIM]  164.7 23.02 270 bottom
J22  WJ15EDGRC-3.81-4P  [DB2ERC-3P81-4P]  115.43 13.05 180 top
J23  MINI-PCIE  [PCIE_52P]  132.7 67.98 180 top
J24  TF_Card  [TFCARD]  169 21.69 90 top
J25  -  [HDR1X3-2R54-TM-VM]  1.8 17.72 270 top
J26  1.25T-2A  [GH1P25_TH_2P]  112.65 41 180 top
J27  CON6  [DB2ERC-3P81-6P]  135.73 13.05 180 top
J28  PH-4A  [PH-1X4-2P0]  113.25 22.49 90 top
J29  PH-4A  [PH-1X4-2P0]  105.83 22.53 270 top
J30  -  [HDR2X3-2R54-TM-VM]  112.65 32.78 270 top
J31  -  [HDR2X3-2R54-TM-VM]  106.43 32.78 270 top
J32  FPC_0P5_24P_D  [FPC_24P_0P5]  167.29 75.6 270 top
J33  FPC_0P5_24P_D  [FPC_24P_0P5]  167.29 75.6 90 bottom
J34  FPC_0P5_24P_D  [FPC_24P_0P5]  167.29 58.21 270 top
J35  FPC_0P5_24P_D  [FPC_24P_0P5]  167.29 58.21 90 bottom
J36  FPC_0P5_24P_D  [FPC_24P_0P5]  167.29 40.81 270 top
J37  FPC_0P5_24P_D  [FPC_24P_0P5]  167.29 40.81 90 bottom
J38  XH-4A  [XH2P54-4P]  65.02 11.04 0 top
J39  SATA  [SSATA_V]  80.54 9.75 180 top
J40  CON2  [DB2ERC-3P81-2P]  93.87 12.55 180 top
J41  PH-5A  [PH-1X5-2P0]  51.49 10.7 180 top
J42  PH-2A  [PH-1X2-2P0_L]  26.16 86.69 180 top
J43  PH-2A  [PH-1X2-2P0_L]  37.45 86.69 180 top
J44  PH-6A  [PH-1X6-2P0]  37.47 10.7 180 top
J45  CON2  [DB2ERC-3P81-2P]  102.74 12.55 180 top
L1  100R 100MHz  [L0603]  14.86 100.07 270 bottom
L2  3.3uH  [L4520]  23.62 57.41 270 top
L3  1.5uH  [L0518]  24.18 27.95 270 top
L4  2.2uH  [L2520]  74.14 72.4 0 top
L7  2.2uH  [L2520]  55.74 72.4 0 top
L11  100R 100MHz  [L0603]  113.67 100.46 180 bottom
L12  100R 100MHz  [L0603]  33.53 101.47 0 bottom
L13  100R 100MHz  [L0603]  134.62 100.2 90 bottom
L14  100R 100MHz  [L0603]  18.54 70.25 180 bottom
L15  100R 100MHz  [L0603]  21.72 70.25 0 bottom
L16  3.3uH  [L4520]  152.53 75.7 90 top
L17  3.3uH  [L4520]  23.62 45.34 270 top
L18  3.3uH  [L4520]  152.66 60.21 90 top
L19  1K 100MHz  [L0603]  28.19 80.53 90 top
L20  3.3uH  [L4520]  13.71 68.47 270 top
L21  3.3uH  [L4520]  23.49 51.43 0 top
L22  100R 100MHz  [L0603]  144.53 27.94 0 bottom
L23  100R 100MHz  [L0603]  136.65 27.94 0 bottom
L24  100R 100MHz  [L0603]  128.06 22.22 180 bottom
L25  3.3uH  [L4520]  157.99 60.21 0 top
L26  3.3uH  [L4520]  23.75 35.69 270 top
L27  1K 100MHz  [L0603]  24.38 80.53 90 top
L28  1K 100MHz  [L0603]  39.5 80.53 90 top
L29  1K 100MHz  [L0603]  35.69 80.53 90 top
LED1  HS-0602-UR  [LED_HS_0602_UR]  151.47 101.4 0 top
LED2  HS-0602-UG  [LED_HS_0602_UR]  156.03 101.4 0 top
NOREF  -  [unnamed]  30.71 28.54 0 top
NOREF#2  -  [unnamed]  152.22 105.5 180 top
NOREF#3  -  [unnamed]  10.01 97.12 0 top
NOREF#4  -  [#2]  2 8 90 top
NOREF#5  -  [unnamed]  20.78 105.5 180 top
NOREF#6  -  [#2]  0 10 0 top
NOREF#7  -  [unnamed]  152.22 4.5 0 top
NOREF#8  -  [#2]  39.12 21.84 0 top
NOREF#9  -  [unnamed]  159.18 67.48 0 top
NOREF#10  -  [unnamed]  28.4 4.5 0 top
NOREF#11  -  [unnamed]  152.25 10.23 0 top
NOREF#12  -  [unnamed]  15.72 20.56 0 bottom
NOREF#13  -  [unnamed]  156.01 96.08 0 bottom
NOREF#14  -  [unnamed]  28.4 4.5 0 bottom
NOREF#15  -  [unnamed]  152.22 4.5 0 bottom
NOREF#16  -  [unnamed]  27.97 92.32 0 bottom
NOREF#17  -  [unnamed]  152.22 105.5 0 bottom
NOREF#18  -  [unnamed]  148.51 15.71 0 bottom
NOREF#19  -  [unnamed]  20.78 105.5 0 bottom
P1  MIC_POM  [MIC2-4R00-TM]  3.43 93.05 0 top
Q1  SSM3J328R-LF  [SOT23]  99.95 37.75 180 bottom
Q2  SS8050  [SOT23]  99.95 28.6 180 bottom
Q3  WNM2016-3/TR  [SOT23]  40.02 94.23 90 bottom
Q4  WNM2016-3/TR  [SOT23]  33.52 94.23 270 bottom
Q5  SSM3J328R-LF  [SOT23]  12.71 20.7 270 top
Q6  2SK3018  [SOT23]  84.58 73.94 0 top
Q7  2SK3018  [SOT23]  88.76 72.15 270 bottom
Q8  2SK3018  [SOT23]  92.44 68.98 270 bottom
Q9  2SK3018  [SOT23]  88.76 68.98 270 bottom
Q10  2SK3018  [SOT23]  95.36 72.15 270 bottom
Q11  2SK3018  [SOT23]  104 72.13 270 bottom
Q12  2SK3018  [SOT23]  99.94 72.13 270 bottom
Q13  2SK3018  [SOT23]  104 68.71 270 bottom
Q14  2SK3018  [SOT23]  81.53 73.94 0 top
Q15  2SK3018  [SOT23]  109.33 72.13 270 bottom
Q16  2SK3018  [SOT23]  117.08 72.13 270 bottom
Q17  2SK3018  [SOT23]  117.08 68.58 270 bottom
Q18  2SK3018  [SOT23]  117.08 65.15 270 bottom
Q19  2SK3018  [SOT23]  120.76 76.71 270 bottom
Q20  2SK3018  [SOT23]  109.84 76.71 270 bottom
Q21  2SK3018  [SOT23]  113.53 76.71 270 bottom
Q22  2SK3018  [SOT23]  117.08 76.71 270 bottom
Q23  2SK3018  [SOT23]  109.33 68.71 270 bottom
Q24  2SK3018  [SOT23]  126.24 81.27 180 top
Q25  2SK3018  [SOT23]  129.54 81.27 180 top
Q26  2SK3018  [SOT23]  122.94 81.27 180 top
Q27  SSM3J328R-LF  [SOT23]  132.84 81.27 180 top
Q28  SS8050  [SOT23]  132.84 81.27 0 bottom
Q29  SS8050  [SOT23]  119.51 81.27 180 top
Q30  SSM3J328R-LF  [SOT23]  22.62 40.38 270 top
Q31  SS8050  [SOT23]  17.54 40.38 270 top
Q32  SS8050  [SOT23]  12.56 24.13 90 top
Q33  2SK3018  [SOT23]  145.66 34.92 90 top
Q34  2SK3018  [SOT23]  141.72 34.92 90 top
Q35  SS8050  [SOT23]  156.21 97.93 0 top
R1  100R  [R0402]  25.91 15.38 90 top
R2  100R  [R0402]  22.61 15.89 0 top
R3  10K  [R0402]  120.4 34.94 270 bottom
R4  115K  [R0402]  18.54 55.88 0 bottom
R5  100R  [R0402]  20.19 15.89 0 top
R6  1K  [R0402]  16.51 55.88 180 bottom
R7  20K  [R0402]  18.54 57.91 0 bottom
R8  3.3R  [R0402]  20.07 30.5 90 top
R9  510K  [R0402]  14.99 31 0 bottom
R10  NC  [R0402]  22.86 32.78 180 bottom
R11  4.7K  [R0402]  151.26 98.55 0 top
R12  43K  [R0402]  19.81 31.77 180 bottom
R13  NC  [R0402]  19.81 32.78 0 bottom
R14  100K  [R0402]  18.29 28.46 0 bottom
R15  100K  [R0402]  16.76 27.96 270 bottom
R16  100K  [R0402]  14.99 29.99 180 bottom
R17  7.5K  [R0402]  18.29 32.27 90 bottom
R18  NC  [R0402]  18.29 27.45 180 bottom
R19  100R  [R0402]  12.83 15.89 0 top
R20  4.7K  [R0402]  69.09 72.28 270 bottom
R21  4.7K  [R0402]  67.94 72.28 270 bottom
R22  4.7K  [R0402]  65.91 72.28 270 bottom
R23  22R  [R0402]  69.03 72.13 90 top
R24  22R  [R0402]  68.01 72.13 90 top
R25  2.49K  [R0402]  73.13 79.52 180 bottom
R26  22R  [R0402]  67 72.13 90 top
R27  22R  [R0402]  65.98 72.13 90 top
R28  22R  [R0402]  71.06 72.13 90 top
R29  22R  [R0402]  70.04 72.13 90 top
R30  4.7K  [R0402]  67.18 69.61 270 bottom
R31  4.7K  [R0402]  71.12 72.28 90 bottom
R32  4.7K  [R0402]  70.1 72.28 90 bottom
R33  4.7K  [R0402]  64.64 80.53 0 bottom
R34  4.7K  [R0402]  64.64 79.52 0 bottom
R35  4.7K  [R0402]  73.15 75.07 0 bottom
R36  115K  [R0402]  13.21 72.39 270 bottom
R37  22R  [R0402]  75.44 76.72 90 bottom
R38  NC  [R0402]  76.45 76.72 90 bottom
R39  510R  [R0603]  69.85 95.38 0 bottom
R40  510R  [R0603]  73.03 95.38 180 bottom
R41  10K  [R0402]  67.69 77.99 90 bottom
R42  1M  [R0805]  70.1 92.71 90 bottom
R43  4.7K  [R0402]  75.95 79.52 0 bottom
R44  4.7K  [R0402]  75.44 76.34 90 top
R45  4.7K  [R0402]  73.15 76.09 180 bottom
R46  0R  [R0402]  76.45 74.18 270 top
R47  0R  [R0402]  77.47 74.18 90 top
R48  4.7K  [R0402]  50.42 72.4 270 bottom
R49  4.7K  [R0402]  49.4 72.4 270 bottom
R50  4.7K  [R0402]  48.26 72.4 270 bottom
R51  22R  [R0402]  50.37 72.13 90 top
R52  22R  [R0402]  49.36 72.13 90 top
R53  2.49K  [R0402]  54.73 79.52 180 bottom
R54  22R  [R0402]  48.34 72.13 90 top
R55  22R  [R0402]  47.33 72.13 90 top
R56  22R  [R0402]  52.41 72.13 90 top
R57  22R  [R0402]  51.39 72.13 90 top
R58  4.7K  [R0402]  48.26 69.74 270 bottom
R59  4.7K  [R0402]  52.45 72.4 90 bottom
R60  4.7K  [R0402]  51.44 72.4 90 bottom
R61  4.7K  [R0402]  46.22 80.53 0 bottom
R62  4.7K  [R0402]  46.22 79.52 0 bottom
R63  4.7K  [R0402]  54.74 75.2 0 bottom
R64  510R  [R0603]  58.17 79.52 270 bottom
R65  1K  [R0402]  11.18 72.39 270 bottom
R66  510R  [R0603]  52.7 98.93 0 bottom
R67  100R  [R0402]  57.28 76.72 90 bottom
R68  120R  [R0402]  58.29 76.72 90 bottom
R69  10K  [R0402]  43.05 80.53 0 bottom
R70  NC  [R0402]  44.7 80.02 90 bottom
R71  1M  [R0805]  51.56 92.58 90 bottom
R72  4.7K  [R0402]  57.66 76.34 90 top
R73  4.7K  [R0402]  54.74 77.23 180 bottom
R74  4.7K  [R0402]  54.74 76.21 180 bottom
R75  0R  [R0402]  59.69 74.18 270 top
R76  0R  [R0402]  58.67 74.18 90 top
R77  4.7K  [R0402]  62.1 71.64 180 top
R78  NC  [R0402]  62.1 72.66 180 top
R79  2.2R  [R0402]  121.67 82.55 270 bottom
R80  2.2R  [R0402]  120.65 82.55 270 bottom
R81  2.2R  [R0402]  26.67 91.69 270 top
R82  2.2R  [R0402]  25.15 91.69 270 top
R83  0R  [R0402]  119.63 82.55 270 bottom
R84  0R  [R0402]  118.62 82.55 270 bottom
R85  0R  [R0402]  29.72 91.69 270 top
R86  0R  [R0402]  30.73 91.69 270 top
R87  10K  [R0402]  18.92 83.45 0 top
R88  2.2R  [R0402]  125.22 82.55 270 bottom
R89  0R  [R0402]  23.11 91.69 270 top
R90  2.2R  [R0402]  124.21 82.55 270 bottom
R91  0R  [R0402]  24.13 91.69 270 top
R92  100K  [R0402]  23.75 92.45 0 bottom
R93  1K  [R0402]  15.24 82.69 90 bottom
R94  100K  [R0402]  21.72 92.45 180 bottom
R95  3.4K  [R0402]  17.2 89.31 90 bottom
R96  1K  [R0402]  116.97 100.2 90 bottom
R97  NC  [R0402]  23.75 93.47 0 bottom
R98  NC  [R0402]  21.72 93.47 180 bottom
R99  3.4K  [R0402]  118.49 99.69 180 bottom
R100  0R  [R0402]  136.78 76.71 90 bottom
R101  10K  [R0402]  136.14 79.5 180 top
R102  1K  [R0402]  138.18 101.47 0 bottom
R103  3.4K  [R0402]  138.18 98.93 180 bottom
R104  100K  [R0402]  136.14 77.21 180 top
R105  100K  [R0402]  136.14 80.64 180 top
R106  2.2R  [R0402]  136.14 81.79 180 top
R107  2.2R  [R0402]  136.14 82.8 180 top
R108  2.7K  [R0402]  136.14 83.82 180 top
R109  10K  [R0402]  161.16 97.41 90 top
R110  22R  [R0402]  160.02 97.41 90 top
R111  22R  [R0402]  164.72 97.41 270 top
R112  4.7R  [R0402]  23.24 73.55 90 bottom
R113  100R  [R0402]  37.85 96.39 0 bottom
R114  0R  [R0402]  37.34 98.42 270 bottom
R115  2.2K  [R0402]  33.02 98.93 180 bottom
R116  100K  [R0402]  33.02 99.95 0 bottom
R117  0R  [R0402]  38.35 98.42 270 bottom
R118  100K  [R0402]  35.43 99.95 0 bottom
R119  100K  [R0402]  41.4 100.46 270 bottom
R120  0R  [R0402]  40.39 100.46 90 bottom
R121  10K  [R0402]  18.41 81.04 270 top
R122  0R  [R0402]  39.62 91.44 270 bottom
R123  470R  [R0402]  40.64 91.44 270 bottom
R124  0R  [R0402]  32.51 91.44 270 bottom
R125  100R  [R0402]  2.92 89.15 270 bottom
R126  1.1K  [R0402]  1.91 88.01 90 top
R127  0R  [R0805]  99.95 34.69 180 bottom
R128  4.7K  [R0402]  153.42 98.55 0 top
R129  0R  [R0805]  99.95 40.78 0 bottom
R130  0R  [R0402]  2.92 88.01 270 top
R131  NC  [R0805]  99.95 32.65 180 bottom
R132  10K  [R0402]  99.95 31 0 bottom
R133  1K  [R0402]  99.95 25.29 0 bottom
R134  0R  [R0402]  3.94 88.01 270 top
R135  10K  [R0402]  99.95 26.3 180 bottom
R136  1.1K  [R0402]  4.95 88.01 270 top
R137  0R  [R0402]  11.56 41.02 90 top
R138  100K  [R0402]  157.99 55.89 180 bottom
R139  10K  [R0402]  157.99 52.85 180 bottom
R140  1K  [R0402]  157.99 53.86 180 bottom
R141  30K  [R0402]  157.99 54.88 180 bottom
R142  2.2R  [R0402]  141.99 76.71 270 bottom
R143  2.2R  [R0402]  140.97 76.71 270 bottom
R144  1K  [R0402]  129.29 60.7 270 bottom
R145  22R  [R0402]  129.03 76.83 270 bottom
R146  1K  [R0402]  128.27 60.7 270 bottom
R147  4.7K  [R0402]  128.02 76.83 270 bottom
R148  22R  [R0402]  127 76.83 270 bottom
R149  20K  [R0402]  129.67 100.2 270 bottom
R150  10K  [R0402]  128.65 100.2 90 bottom
R151  4.7K  [R0402]  84.58 71.64 0 top
R152  4.7K  [R0402]  83.06 76.47 0 top
R153  1K  [R0402]  92.46 72.66 180 bottom
R154  4.7K  [R0402]  92.46 71.64 180 bottom
R155  4.7K  [R0402]  86.36 72.15 90 bottom
R156  0R  [R0402]  82.55 100.71 90 bottom
R157  47K  [R0402]  92.46 66.82 180 bottom
R158  47K  [R0402]  94.74 68.98 90 bottom
R159  1.2K  [R0402]  85.85 77.48 90 bottom
R160  47K  [R0402]  86.36 69.1 270 bottom
R161  499R  [R0402]  88.27 77.48 270 bottom
R162  499R  [R0402]  89.28 77.48 270 bottom
R163  499R  [R0402]  95 77.48 270 bottom
R164  499R  [R0402]  96.01 77.48 270 bottom
R165  499R  [R0402]  92.84 77.48 270 bottom
R166  499R  [R0402]  93.85 77.48 270 bottom
R167  499R  [R0402]  90.55 77.48 270 bottom
R168  499R  [R0402]  91.57 77.48 270 bottom
R169  1K  [R0402]  104.14 65.28 0 bottom
R170  27K  [R0402]  81.53 71.64 0 top
R171  10K  [R0402]  104.14 66.29 180 bottom
R172  4.7K  [R0402]  111.51 72.13 270 bottom
R173  10K  [R0402]  106.93 72.26 90 bottom
R174  1K  [R0402]  120.27 73.15 270 bottom
R175  4.7K  [R0402]  120.27 71.12 90 bottom
R176  10K  [R0402]  114.68 72.13 90 bottom
R177  0R  [R0402]  93.34 100.71 90 bottom
R178  47K  [R0402]  114.68 68.71 270 bottom
R179  47K  [R0402]  114.68 65.15 90 bottom
R180  1.2K  [R0402]  97.28 77.48 90 bottom
R181  47K  [R0402]  119.25 65.15 270 bottom
R182  499R  [R0402]  99.57 77.48 270 bottom
R183  499R  [R0402]  100.58 77.48 270 bottom
R184  499R  [R0402]  106.3 77.48 270 bottom
R185  499R  [R0402]  107.31 77.48 270 bottom
R186  499R  [R0402]  104.01 77.48 270 bottom
R187  499R  [R0402]  105.03 77.47 270 bottom
R188  499R  [R0402]  101.73 77.48 270 bottom
R189  499R  [R0402]  102.74 77.48 270 bottom
R190  1K  [R0402]  124.59 76.83 90 bottom
R191  27K  [R0402]  111.51 68.71 270 bottom
R192  10K  [R0402]  123.57 76.83 270 bottom
R193  100K  [R0402]  120.52 77.47 90 top
R194  22K  [R0402]  119.51 77.47 270 top
R195  0R  [R0402]  110.62 100.2 90 bottom
R196  10K  [R0402]  126.36 83.95 180 top
R197  47K  [R0402]  127 76.96 0 top
R198  56K  [R0402]  129.67 83.95 180 top
R199  10K  [R0402]  123.06 83.95 180 top
R200  47K  [R0402]  127 77.98 0 top
R201  2.2R  [R0402]  117.09 77.47 90 top
R202  2.2R  [R0402]  116.08 77.47 90 top
R203  2.2R  [R0402]  115.57 75.44 90 top
R204  2.2R  [R0402]  114.55 75.44 90 top
R205  2.2R  [R0402]  113.03 77.47 90 top
R206  2.2R  [R0402]  112.01 77.47 90 top
R207  2.2R  [R0402]  111.51 75.44 90 top
R208  2.2R  [R0402]  110.49 75.44 90 top
R209  56K  [R0402]  128.91 77.47 90 top
R210  100K  [R0402]  118.49 77.47 90 top
R211  20K  [R0402]  129.79 82.55 90 bottom
R212  10K  [R0402]  128.78 82.55 270 bottom
R213  100K  [R0402]  132.84 83.95 0 top
R214  1K  [R0402]  132.84 78.99 180 bottom
R215  10K  [R0402]  132.84 83.44 180 bottom
R216  33R  [R0402]  102.62 43.56 180 top
R217  33R  [R0402]  102.62 44.58 180 top
R218  100K  [R0402]  152.53 71.39 180 bottom
R219  49.9R  [R0402]  102.62 44.59 0 bottom
R220  49.9R  [R0402]  102.62 43.58 0 bottom
R221  1K  [R0402]  152.53 69.36 180 bottom
R222  10K  [R0402]  152.53 68.34 180 bottom
R223  10K  [R0402]  113.67 47.51 90 bottom
R224  4.7K  [R0402]  114.68 47.51 90 bottom
R225  10K  [R0402]  113.67 45.48 270 bottom
R226  10K  [R0402]  114.68 45.48 270 bottom
R227  30K  [R0402]  152.53 70.37 180 bottom
R228  33R  [R0402]  102.62 45.59 180 top
R229  33R  [R0402]  102.62 46.61 180 top
R230  22R  [R0402]  117.09 47.37 180 top
R231  49.9R  [R0402]  102.62 46.62 0 bottom
R232  49.9R  [R0402]  102.62 45.61 0 bottom
R233  10K  [R0402]  117.09 44.96 0 top
R234  470R  [R0402]  117.09 49.66 0 top
R235  2.2R  [R0402]  108.71 47.51 270 bottom
R236  10K  [R0402]  154.05 82.82 270 top
R237  10K  [R0402]  161.04 82.82 270 top
R238  33R  [R0402]  102.62 47.62 180 top
R239  33R  [R0402]  102.62 48.64 180 top
R240  49.9R  [R0402]  102.62 48.66 0 bottom
R241  49.9R  [R0402]  102.62 47.64 0 bottom
R242  33R  [R0402]  102.62 50.8 180 top
R243  33R  [R0402]  102.62 49.78 180 top
R244  49.9R  [R0402]  100.58 49.54 180 top
R245  49.9R  [R0402]  100.58 51.07 180 top
R246  1K  [R0402]  128.27 34.05 270 bottom
R247  0R  [R0402]  10.79 50.54 270 top
R248  0R  [R0402]  10.79 45.72 270 top
R249  100K  [R0402]  18.67 44.19 0 bottom
R250  30K  [R0402]  18.67 46.23 0 bottom
R251  1K  [R0402]  16.38 44.19 180 bottom
R252  10K  [R0402]  16.38 45.21 180 bottom
R253  15K  [R0402]  148.84 24.78 0 bottom
R254  100K  [R0402]  152.65 55.89 0 bottom
R255  10K  [R0402]  20.07 40.26 90 top
R256  1K  [R0402]  14.48 40.65 0 top
R257  10K  [R0402]  14.48 39.64 180 top
R258  0R  [R0402]  148.84 28.21 0 bottom
R259  0R  [R0402]  148.84 27.07 0 bottom
R260  0R  [R0402]  148.84 25.92 0 bottom
R261  30K  [R0402]  152.65 54.88 180 bottom
R262  1K  [R0402]  152.65 53.86 0 bottom
R263  10K  [R0402]  152.65 52.85 180 bottom
R264  4.7K  [R0402]  144.53 76.71 270 bottom
R265  22R  [R0402]  145.54 76.71 270 bottom
R266  22R  [R0402]  143 76.71 270 bottom
R267  1K  [R0402]  134.11 59.82 270 top
R268  1K  [R0402]  133.1 59.82 270 top
R269  2.2R  [R0402]  127.38 59.82 270 top
R270  2.2R  [R0402]  126.36 59.82 270 top
R271  20K  [R0402]  14.22 72.39 270 bottom
R272  100K  [R0402]  18.8 50.16 0 bottom
R273  1K  [R0402]  16.76 50.16 180 bottom
R274  30K  [R0402]  18.8 52.2 0 bottom
R275  22R  [R0402]  152.78 25.03 0 top
R276  10K  [R0402]  119.38 34.94 90 bottom
R277  22R  [R0402]  118.36 34.94 270 bottom
R278  22R  [R0402]  152.78 23.76 0 top
R279  22R  [R0402]  152.78 22.49 0 top
R280  0R  [R0402]  152.78 19.83 0 top
R281  22R  [R0402]  152.78 18.56 0 top
R282  22R  [R0402]  152.78 17.29 0 top
R283  100R  [R0402]  152.78 16.02 0 top
R284  NC  [R0402]  150.37 16.02 0 top
R285  0R  [R0402]  155.32 14.75 180 top
R286  0R  [R0402]  163.07 82.82 270 top
R287  4.7K  [R0402]  141.22 25.91 270 top
R288  120R  [R0402]  141.22 28.07 270 top
R289  10K  [R0603]  144.78 32.76 0 bottom
R290  100R  [R0402]  4.95 19.7 90 top
R291  100R  [R0402]  4.95 15.64 270 top
R292  4.7K  [R0402]  141.22 30.22 90 top
R293  4.7K  [R0402]  133.48 25.91 270 top
R294  120R  [R0402]  133.48 28.07 270 top
R295  10K  [R0603]  136.65 30.48 0 bottom
R296  4.7K  [R0402]  133.48 30.22 90 top
R297  100R  [R0402]  101.73 29.99 270 top
R298  100R  [R0402]  101.73 26.68 90 top
R299  100R  [R0402]  101.73 35.57 270 top
R300  100R  [R0402]  101.73 32.78 270 top
R301  NC  [R0402]  11.43 77.74 180 bottom
R302  NC  [R0402]  11.18 70.25 90 bottom
R303  NC  [R0402]  11.43 78.75 180 bottom
R304  NC  [R0402]  12.19 70.25 90 bottom
R305  1K  [R0402]  27.69 64.66 180 top
R306  1K  [R0402]  12.95 82.69 90 bottom
R307  3.4K  [R0402]  21.28 62.7 180 top
R308  3.4K  [R0402]  14.02 89.31 90 bottom
R309  3.4K  [R0402]  10.85 89.31 90 bottom
R310  3.4K  [R0402]  12.64 62.7 180 top
R311  0R  [R0402]  163.07 68.47 90 bottom
R312  0R  [R0402]  163.07 65.42 270 top
R313  0R  [R0402]  163.07 51.07 90 bottom
R314  0R  [R0402]  163.07 48.02 270 top
R315  0R  [R0402]  163.07 33.54 90 bottom
R316  115K  [R0402]  18.54 34.42 0 bottom
R317  10K  [R0402]  16.51 35.43 180 bottom
R318  1K  [R0402]  16.51 34.42 180 bottom
R319  10K  [R0402]  10.41 20.7 90 top
R320  1K  [R0402]  12.19 26.8 270 top
R321  10K  [R0402]  13.46 26.8 90 top
R322  20K  [R0402]  18.54 36.45 0 bottom
R323  3.4K  [R0402]  122.94 97.03 270 bottom
R324  1K  [R0402]  127.64 100.2 90 bottom
R325  470R  [R0402]  31.5 91.44 270 bottom
R326  300K  [R0402]  33.02 96.52 180 bottom
R327  0R  [R0402]  33.02 97.53 0 bottom
R328  10K  [R0402]  10.54 41.02 90 top
R329  2.2K  [R0402]  146.69 35.05 90 bottom
R330  10K  [R0402]  144.78 35.05 90 bottom
R331  10K  [R0402]  140.72 35.05 90 bottom
R332  2.2K  [R0402]  142.75 35.05 90 bottom
R333  120R  [R0402]  117.86 27.95 270 top
R334  1K  [R0402]  151.26 96.9 0 top
R335  10K  [R0402]  153.42 96.9 180 top
R336  25.5K  [R0402]  38.23 64.53 90 top
R337  10K  [R0402]  39.5 64.53 270 top
R338  100R  [R0402]  53.09 14.87 0 bottom
R339  100R  [R0402]  51.05 14.87 0 bottom
R340  100R  [R0402]  49.02 14.87 0 bottom
R341  0R  [R0603]  33.53 70.63 180 top
R342  NC  [R0603]  30.48 70.63 0 top
R343  20K  [R0402]  28.19 70.88 90 top
R344  20K  [R0402]  26.92 70.88 90 top
R345  1K  [R0402]  24.89 69.1 180 top
R346  10K  [R0402]  24.38 70.88 270 top
R347  0R  [R0603]  44.98 71.8 180 top
R348  NC  [R0603]  41.94 71.8 0 top
R349  20K  [R0402]  39.5 70.88 90 top
R350  20K  [R0402]  38.23 70.88 90 top
R351  1K  [R0402]  36.96 68.47 90 top
R352  10K  [R0402]  35.69 70.88 270 top
R353  10K  [R0402]  134.37 46.5 270 bottom
R354  27K  [R0402]  106.93 68.71 90 bottom
R355  120R  [R0402]  125.86 27.94 270 top
R356  2.2K  [R0402]  87.12 15.25 90 top
R357  2.2K  [R0402]  88.14 15.25 90 top
R358  2.2K  [R0402]  85.09 15.25 90 top
R359  2.2K  [R0402]  86.11 15.25 90 top
R360  2.2K  [R0402]  77.47 15.25 90 top
R361  2.2K  [R0402]  78.49 15.25 90 top
R362  0R  [R0402]  47.37 15.38 90 top
R363  0R  [R0402]  79.5 72.15 270 top
R364  0R  [R0402]  78.36 82.18 0 top
R365  0R  [R0201]  72.76 82.18 90 top
R366  0R  [R0201]  72.12 82.18 90 top
R367  0R  [R0201]  71.49 82.18 90 top
R368  0R  [R0201]  70.85 82.18 90 top
R369  0R  [R0201]  70.22 82.18 90 top
R370  0R  [R0201]  69.58 82.18 90 top
R371  0R  [R0201]  68.95 82.18 90 top
R372  0R  [R0201]  68.31 82.18 90 top
R373  0R  [R0201]  54.36 82.18 90 top
R374  0R  [R0201]  53.72 82.18 90 top
R375  0R  [R0201]  53.09 82.18 90 top
R376  0R  [R0201]  52.45 82.18 90 top
R377  0R  [R0201]  51.82 82.18 90 top
R378  0R  [R0201]  51.18 82.18 90 top
R379  0R  [R0201]  50.55 82.18 90 top
R380  0R  [R0201]  49.91 82.18 90 top
R381  0R  [R0402]  62.1 73.67 0 top
R382  0R  [R0402]  55.24 72.28 270 bottom
R383  0R  [R0402]  60.71 82.18 0 top
R384  22R  [R0402]  75.95 79.9 180 top
R385  1M  [R0402]  75.44 78.37 270 top
R386  1M  [R0402]  57.66 78.37 270 top
R387  22R  [R0402]  58.17 79.9 180 top
SS1  -  [NPTH_M3]  3.5 10.5 0 top
SS2  -  [NPTH_M3]  3.5 99.5 0 top
SS3  -  [NPTH_M3]  169.5 99.5 0 top
SS4  -  [NPTH_M3]  169.5 10.5 0 top
SS5  M2.5X1.5mm  [SMTSO-M2R5]  32.06 66.53 0 top
SS6  M2.5X1.5mm  [SMTSO-M2R5]  98.06 66.53 0 top
SS7  M2.5X1.5mm  [SMTSO-M2R5]  32.06 20.53 0 top
SS8  M2.5X1.5mm  [SMTSO-M2R5]  98.06 20.53 0 top
SS9  M2X3mm  [T3R2-5R2_TOPSMT]  120.6 19.93 0 top
SS10  M2X3mm  [T3R2-5R2_TOPSMT]  144.8 19.93 0 top
SS11  M3X3.5mm  [SMTSO-M3]  161.04 10.46 0 top
SS12  M3X3.5mm  [SMTSO-M3]  132.83 38.01 180 bottom
SW1  TS-1091B-A5B3-D2  [SW_TH_3P_4R5X5R5]  27 10.57 0 top
SW2  TS-1091B-A5B3-D2  [SW_TH_3P_4R5X5R5]  21.16 10.57 0 top
SW3  TS-1091B-A5B3-D2  [SW_TH_3P_4R5X5R5]  15.32 10.57 0 top
SW4  TS-1091B-A5B3-D2  [SW_TH_3P_4R5X5R5]  9.48 10.57 0 top
U1  ASP9135ZC-R  [SOT23_6]  17.53 57.28 180 top
U2  MP8759GD-Z  [QFN12-2R00X3R00]  17.53 28.72 0 top
U3  RTL8211F  [QFP_40P_R]  52.06 77.87 270 top
U4  RTL8211F  [QFP_40P_R]  70.46 77.87 270 top
U5  FUSB302BMPX  [WQFN14-0R50-2R5X2R5EP1R45X1R45]  19.94 86.37 0 top
U6  LPW5209AB5F  [SOT23-5]  16.18 86.05 0 bottom
U7  LPW5209AB5F  [SOT23-5]  121.16 100.2 180 bottom
U8  RCLAMP0524P  [USON_10]  29.21 93.72 0 top
U9  RCLAMP0524P  [USON_10]  22.61 93.72 0 top
U10  RCLAMP0524P  [USON_10]  120.14 84.58 0 bottom
U11  RCLAMP0524P  [USON_10]  125.73 84.58 0 bottom
U12  RCLAMP0524P  [USON_10]  141.1 85.34 0 top
U13  LPW5209AB5F  [SOT23-5]  141.1 100.2 180 bottom
U14  FE1.1s-BQFN24B  [QFN24]  141.1 80.64 180 top
U15  IRM-V838M3-C/TR1  [SMD4-6R80X2R50]  162.31 99.79 0 top
U16  ES8388  [QFN28_0R45-4X4EP2R6X2R6]  20.45 75.71 0 top
U17  ASP9135ZC-R  [SOT23_6]  157.99 53.86 270 top
U18  LPW5209AB5F  [SOT23-5]  24.32 63.72 270 top
U19  SIT3088EESA  [SOP8]  136.91 27.94 180 top
U23  RCLAMP0524P  [USON_10]  115.82 79.88 0 top
U24  RCLAMP0524P  [USON_10]  111.76 79.88 0 top
U25  ASP9135ZC-R  [SOT23_6]  152.53 69.36 270 top
U26  PI6C557-05BLE  [TSSOP20]  111.12 46.75 90 top
U27  TP5108E23E-33  [SOT23-5]  128.27 35.07 0 top
U28  ASP9135ZC-R  [SOT23_6]  17.53 45.46 180 top
U29  ASP9135ZC-R  [SOT23_6]  152.65 53.86 270 top
